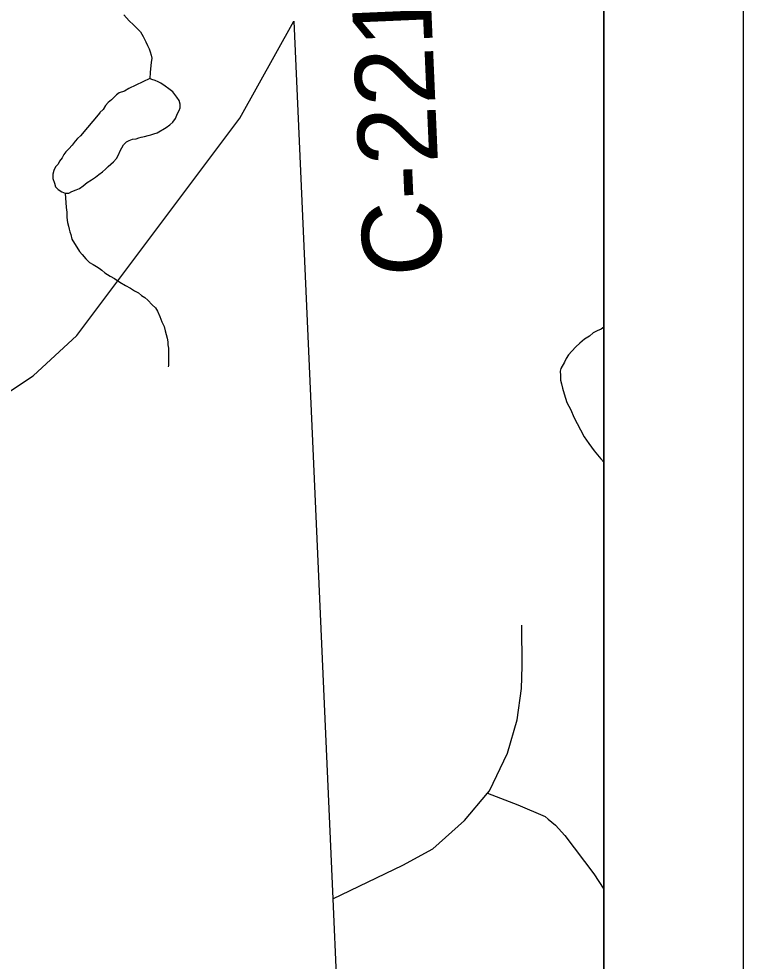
# Model space of a CAD drawing. Extents: x -59 to 82, y -3 to 49.
# Drawn here: x -48.518 to -47.998, y 44.619 to 45.296 of the extents above; entities that cross this region are included whole.
import ezdxf

# ---------------------------------------------------------------- set-up
doc = ezdxf.new("R2010")
doc.units = 0
for name, color, linetype in [('GM_X_Corporation', 7, 'Continuous'), ('GM_X_County_Road', 7, 'Continuous'), ('GM_X_County_Road_Text', 7, 'Continuous'), ('GM_X_Minor_Lake', 7, 'Continuous'), ('GM_X_Minor_River', 7, 'Continuous'), ('GM_X_Township_Road', 7, 'Continuous'), ('SH_Data', 7, 'Continuous')]:
    doc.layers.add(name, color=color, linetype=linetype)

msp = doc.modelspace()

# ---------------------------------------------------------------- linework, layer by layer
at = {"layer": 'GM_X_Corporation'}
for q in [(-48.09799, 49.29125), (-48.09799, 46.29445)]:
    msp.add_line((-48.09799, 42.49125), q, dxfattribs=at)
at = {"layer": 'GM_X_County_Road'}
for p, q in [((-48.35946, 45.22464), (-48.32077, 45.29427)), ((-48.32077, 45.29427), (-48.2928, 44.66418)), ((-48.47659, 45.0687), (-48.35946, 45.22464)), ((-48.50797, 45.03972), (-48.47659, 45.0687)), ((-48.71466, 44.90327), (-48.50797, 45.03972)), ((-48.2928, 44.66418), (-48.27757, 44.31965))]:
    msp.add_line(p, q, dxfattribs=at)
at = {"layer": 'GM_X_Minor_Lake'}
for p, q in [((-48.42411, 45.25316), (-48.43931, 45.24599)), ((-48.42265, 45.25257), (-48.42411, 45.25316)), ((-48.42037, 45.25182), (-48.42265, 45.25257)), ((-48.41808, 45.2507), (-48.42037, 45.25182)), ((-48.41618, 45.24995), (-48.41808, 45.2507)), ((-48.41312, 45.24769), (-48.41618, 45.24995)), ((-48.41045, 45.24581), (-48.41312, 45.24769)), ((-48.44801, 45.24136), (-48.44989, 45.23983)), ((-48.44612, 45.2429), (-48.44801, 45.24136)), ((-48.44233, 45.24406), (-48.44612, 45.2429)), ((-48.43931, 45.24599), (-48.44233, 45.24406)), ((-48.40777, 45.24355), (-48.41045, 45.24581)), ((-48.40624, 45.24166), (-48.40777, 45.24355)), ((-48.4047, 45.23977), (-48.40624, 45.24166)), ((-48.45404, 45.236), (-48.45592, 45.2337)), ((-48.45177, 45.23792), (-48.45404, 45.236)), ((-48.44989, 45.23983), (-48.45177, 45.23792)), ((-48.40316, 45.2375), (-48.4047, 45.23977)), ((-48.40238, 45.23485), (-48.40316, 45.2375)), ((-48.40236, 45.23219), (-48.40238, 45.23485)), ((-48.4602, 45.22852), (-48.47397, 45.21191)), ((-48.46005, 45.22873), (-48.4602, 45.22852)), ((-48.45779, 45.23103), (-48.46005, 45.22873)), ((-48.45592, 45.2337), (-48.45779, 45.23103)), ((-48.40572, 45.22456), (-48.40423, 45.22799)), ((-48.40423, 45.22799), (-48.40311, 45.23028)), ((-48.40311, 45.23028), (-48.40236, 45.23219)), ((-48.40986, 45.21997), (-48.40759, 45.22189)), ((-48.40759, 45.22189), (-48.40572, 45.22456)), ((-48.4212, 45.21343), (-48.41893, 45.21421)), ((-48.41893, 45.21421), (-48.4125, 45.21805)), ((-48.4125, 45.21805), (-48.40986, 45.21997)), ((-48.47773, 45.20808), (-48.47999, 45.20541)), ((-48.47623, 45.21), (-48.47773, 45.20808)), ((-48.47397, 45.21191), (-48.47623, 45.21)), ((-48.44316, 45.20567), (-48.4409, 45.20759)), ((-48.4409, 45.20759), (-48.43901, 45.20874)), ((-48.43901, 45.20874), (-48.43673, 45.20952)), ((-48.43673, 45.20952), (-48.43408, 45.20992)), ((-48.43408, 45.20992), (-48.43219, 45.21069)), ((-48.43219, 45.21069), (-48.43029, 45.21108)), ((-48.43029, 45.21108), (-48.42802, 45.21148)), ((-48.42802, 45.21148), (-48.42536, 45.21226)), ((-48.42536, 45.21226), (-48.42347, 45.21265)), ((-48.42347, 45.21265), (-48.4212, 45.21343)), ((-48.48451, 45.20044), (-48.48601, 45.19852)), ((-48.48225, 45.20273), (-48.48451, 45.20044)), ((-48.47999, 45.20541), (-48.48225, 45.20273)), ((-48.44652, 45.19881), (-48.44578, 45.20071)), ((-48.44578, 45.20071), (-48.44428, 45.20338)), ((-48.44428, 45.20338), (-48.44316, 45.20567)), ((-48.48901, 45.19394), (-48.49013, 45.19166)), ((-48.48713, 45.19624), (-48.48901, 45.19394)), ((-48.48601, 45.19852), (-48.48713, 45.19624)), ((-48.45028, 45.19346), (-48.44801, 45.19576)), ((-48.44801, 45.19576), (-48.44652, 45.19881)), ((-48.49313, 45.18707), (-48.49387, 45.18441)), ((-48.49202, 45.18974), (-48.49313, 45.18707)), ((-48.49013, 45.19166), (-48.49202, 45.18974)), ((-48.45819, 45.18618), (-48.45593, 45.1881)), ((-48.45593, 45.1881), (-48.45404, 45.19001)), ((-48.45404, 45.19001), (-48.45216, 45.19155)), ((-48.45216, 45.19155), (-48.45028, 45.19346)), ((-48.49387, 45.18441), (-48.49385, 45.18137)), ((-48.49385, 45.18137), (-48.49268, 45.17795)), ((-48.46914, 45.1785), (-48.46612, 45.18042)), ((-48.46612, 45.18042), (-48.4631, 45.18235)), ((-48.4631, 45.18235), (-48.46083, 45.18426)), ((-48.46083, 45.18426), (-48.45819, 45.18618)), ((-48.49268, 45.17795), (-48.4919, 45.1753)), ((-48.4919, 45.1753), (-48.48998, 45.17341)), ((-48.48998, 45.17341), (-48.48732, 45.17191)), ((-48.47707, 45.17313), (-48.4748, 45.17428)), ((-48.4748, 45.17428), (-48.47216, 45.1762)), ((-48.47216, 45.1762), (-48.46914, 45.1785)), ((-48.48732, 45.17191), (-48.48503, 45.17079)), ((-48.48503, 45.17079), (-48.48237, 45.17081)), ((-48.48237, 45.17081), (-48.4801, 45.17196)), ((-48.4801, 45.17196), (-48.47707, 45.17313))]:
    msp.add_line(p, q, dxfattribs=at)
at = {"layer": 'GM_X_Minor_River'}
for p, q in [((-48.44277, 45.29879), (-48.43894, 45.29463)), ((-48.43894, 45.29463), (-48.43588, 45.29162)), ((-48.43588, 45.29162), (-48.43358, 45.28935)), ((-48.43358, 45.28935), (-48.4309, 45.28671)), ((-48.4309, 45.28671), (-48.42898, 45.28331)), ((-48.42898, 45.28331), (-48.42705, 45.27952)), ((-48.42705, 45.27952), (-48.42589, 45.27687)), ((-48.42589, 45.27687), (-48.42473, 45.27459)), ((-48.42473, 45.27459), (-48.42395, 45.27232)), ((-48.42395, 45.27232), (-48.42317, 45.27004)), ((-48.42317, 45.27004), (-48.42278, 45.26777)), ((-48.42349, 45.26244), (-48.42383, 45.2575)), ((-48.42313, 45.26472), (-48.42349, 45.26244)), ((-48.42278, 45.26777), (-48.42313, 45.26472)), ((-48.42383, 45.2575), (-48.42411, 45.25316)), ((-48.48503, 45.17079), (-48.48418, 45.16053)), ((-48.48418, 45.16053), (-48.48378, 45.15711)), ((-48.48378, 45.15711), (-48.48375, 45.15331)), ((-48.48375, 45.15331), (-48.48334, 45.1499)), ((-48.48334, 45.1499), (-48.48256, 45.14724)), ((-48.48256, 45.14724), (-48.48216, 45.14496)), ((-48.48216, 45.14496), (-48.48176, 45.14307)), ((-48.48176, 45.14307), (-48.48099, 45.14117)), ((-48.48099, 45.14117), (-48.4802, 45.13776)), ((-48.4802, 45.13776), (-48.47482, 45.12905)), ((-48.47482, 45.12905), (-48.4729, 45.12679)), ((-48.4729, 45.12679), (-48.47022, 45.12377)), ((-48.47022, 45.12377), (-48.46754, 45.12113)), ((-48.46754, 45.12113), (-48.46487, 45.11962)), ((-48.46487, 45.11962), (-48.46258, 45.11812)), ((-48.46258, 45.11812), (-48.46067, 45.11699)), ((-48.46067, 45.11699), (-48.45876, 45.11549)), ((-48.45876, 45.11549), (-48.45647, 45.1136)), ((-48.45647, 45.1136), (-48.45265, 45.11135)), ((-48.45265, 45.11135), (-48.4496, 45.10947)), ((-48.4496, 45.10947), (-48.44578, 45.10684)), ((-48.44578, 45.10684), (-48.44158, 45.10459)), ((-48.44158, 45.10459), (-48.43815, 45.10271)), ((-48.43815, 45.10271), (-48.4351, 45.10083)), ((-48.4351, 45.10083), (-48.43243, 45.09933)), ((-48.43243, 45.09933), (-48.43013, 45.09745)), ((-48.43013, 45.09745), (-48.42784, 45.09594)), ((-48.42784, 45.09594), (-48.42555, 45.09406)), ((-48.42555, 45.09406), (-48.42248, 45.09066)), ((-48.42248, 45.09066), (-48.42018, 45.0884)), ((-48.42018, 45.0884), (-48.41865, 45.08613)), ((-48.41865, 45.08613), (-48.4171, 45.08234)), ((-48.4171, 45.08234), (-48.41555, 45.07855)), ((-48.41555, 45.07855), (-48.414, 45.07514)), ((-48.414, 45.07514), (-48.41322, 45.0721)), ((-48.41322, 45.0721), (-48.41244, 45.06945)), ((-48.10298, 45.07204), (-48.10562, 45.0705)), ((-48.09995, 45.0732), (-48.10298, 45.07204)), ((-48.09799, 45.07453), (-48.09995, 45.0732)), ((-48.41244, 45.06945), (-48.41166, 45.0668)), ((-48.41166, 45.0668), (-48.41126, 45.06414)), ((-48.11204, 45.0659), (-48.11543, 45.06321)), ((-48.10826, 45.0682), (-48.11204, 45.0659)), ((-48.10562, 45.0705), (-48.10826, 45.0682)), ((-48.41126, 45.06414), (-48.41124, 45.06186)), ((-48.41124, 45.06186), (-48.41084, 45.05958)), ((-48.41084, 45.05958), (-48.41082, 45.05654)), ((-48.11807, 45.06053), (-48.12108, 45.05747)), ((-48.11543, 45.06321), (-48.11807, 45.06053)), ((-48.41082, 45.05654), (-48.4108, 45.05426)), ((-48.4108, 45.05426), (-48.41078, 45.05198)), ((-48.41078, 45.05198), (-48.41076, 45.0497)), ((-48.12522, 45.05212), (-48.12634, 45.04945)), ((-48.12334, 45.05479), (-48.12522, 45.05212)), ((-48.12108, 45.05747), (-48.12334, 45.05479)), ((-48.41074, 45.04704), (-48.4109, 45.04605)), ((-48.41076, 45.0497), (-48.41074, 45.04704)), ((-48.12896, 45.04487), (-48.12932, 45.04297)), ((-48.12634, 45.04945), (-48.12896, 45.04487)), ((-48.12932, 45.04297), (-48.1293, 45.03993)), ((-48.1293, 45.03993), (-48.12927, 45.03651)), ((-48.12927, 45.03651), (-48.12849, 45.03385)), ((-48.12849, 45.03385), (-48.12771, 45.03082)), ((-48.12771, 45.03082), (-48.12653, 45.02665)), ((-48.12653, 45.02665), (-48.12458, 45.02058)), ((-48.12458, 45.02058), (-48.12188, 45.01528)), ((-48.12188, 45.01528), (-48.11956, 45.00997)), ((-48.11956, 45.00997), (-48.11725, 45.00543)), ((-48.11725, 45.00543), (-48.11493, 45.00088)), ((-48.11493, 45.00088), (-48.11223, 44.99596)), ((-48.11223, 44.99596), (-48.10878, 44.99105)), ((-48.10878, 44.99105), (-48.10494, 44.98575)), ((-48.10494, 44.98575), (-48.10033, 44.98009)), ((-48.10033, 44.98009), (-48.09799, 44.9776))]:
    msp.add_line(p, q, dxfattribs=at)
at = {"layer": 'GM_X_Township_Road'}
for p, q in [((-48.15671, 44.8312), (-48.15692, 44.86068)), ((-48.15721, 44.81509), (-48.15671, 44.8312)), ((-48.16025, 44.79275), (-48.15721, 44.81509)), ((-48.16732, 44.7688), (-48.16025, 44.79275)), ((-48.18023, 44.74179), (-48.16732, 44.7688)), ((-48.18173, 44.73999), (-48.18023, 44.74179)), ((-48.19817, 44.72028), (-48.18173, 44.73999)), ((-48.18173, 44.73999), (-48.15995, 44.7317)), ((-48.15995, 44.7317), (-48.14026, 44.72313)), ((-48.22082, 44.70013), (-48.19817, 44.72028)), ((-48.14026, 44.72313), (-48.138, 44.72136)), ((-48.138, 44.72136), (-48.1327, 44.71699)), ((-48.1327, 44.71699), (-48.12603, 44.70954)), ((-48.12603, 44.70954), (-48.10527, 44.68209)), ((-48.24247, 44.68818), (-48.22082, 44.70013)), ((-48.2928, 44.66418), (-48.24247, 44.68818)), ((-48.10527, 44.68209), (-48.09799, 44.67117))]:
    msp.add_line(p, q, dxfattribs=at)
at = {"layer": 'SH_Data'}
for p, q in [((-47.99799, 49.39125), (-47.99799, 42.39125)), ((-48.09799, 49.29125), (-48.09799, 42.49125))]:
    msp.add_line(p, q, dxfattribs=at)

# ---------------------------------------------------------------- texts
at = {"layer": 'GM_X_County_Road_Text'}
msp.add_text('C-221', height=0.056818, rotation=92.47729, dxfattribs=at).set_placement((-48.21372, 45.11217))

doc.saveas('drawing.dxf')
